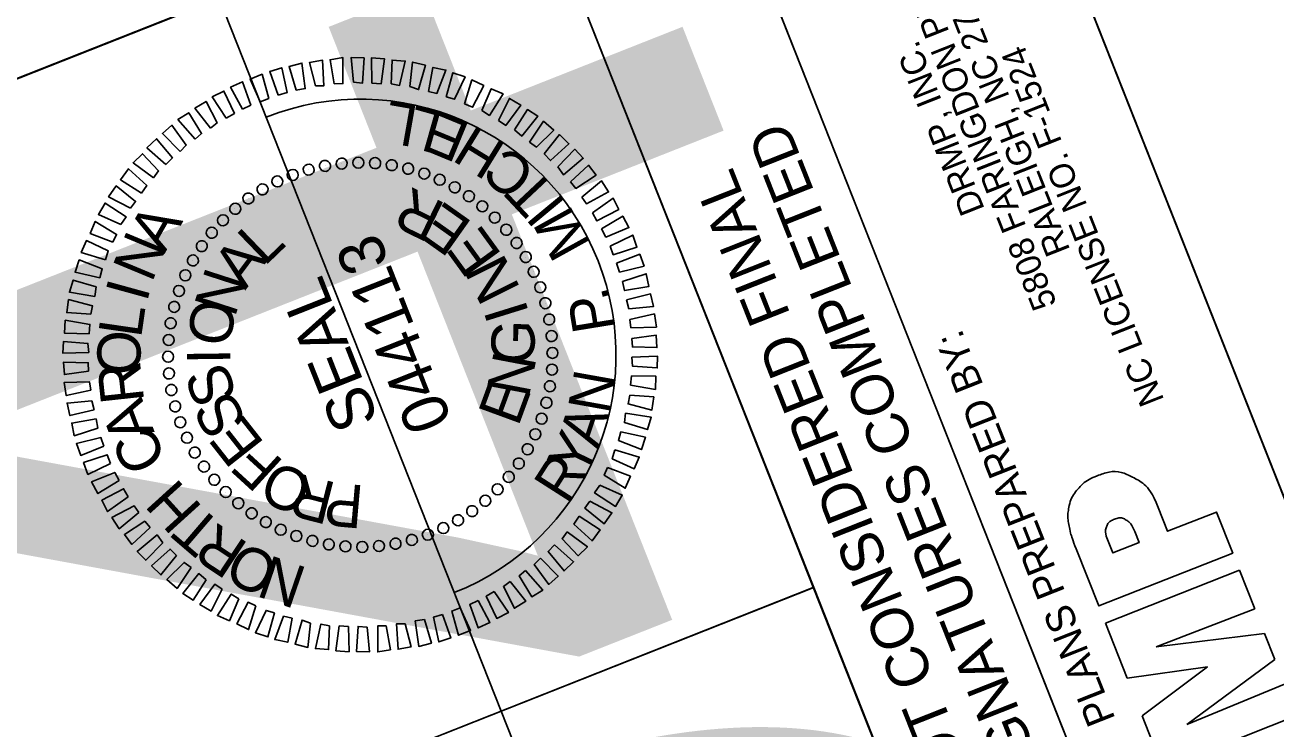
# Model space of a CAD drawing. Extents: x 1250793 to 1252430, y 745882 to 747850.
# Drawn here: x 1250893.3 to 1251056.5, y 747383.5 to 747475.4 of the extents above; entities that cross this region are included whole.
import ezdxf

# ---------------------------------------------------------------- set-up
doc = ezdxf.new("R2010")
doc.units = 0
for name, color, linetype in [('Pattern 1', 7, 'Continuous'), ('Pattern 2', 7, 'Continuous'), ('Scratch_Level_0', 7, 'Continuous'), ('Scratch_Level_1', 7, 'Continuous'), ('Sheet Plan CELL', 7, 'Continuous'), ('Sheet Plan Layout CELL', 7, 'Continuous'), ('Sheet Professional Seal CELL', 7, 'Continuous'), ('Sheet Sticker Exception Certification CELL', 7, 'Continuous')]:
    doc.layers.add(name, color=color, linetype=linetype)

msp = doc.modelspace()

# ---------------------------------------------------------------- linework, layer by layer
at = {"layer": 'Pattern 1'}
for p, q in [((1251034.26, 747397.37), (1251051.74, 747404.28)), ((1251051.74, 747404.28), (1251053.73, 747399.24)), ((1251053.73, 747399.24), (1251040.88, 747394.26)), ((1251037.1, 747390.19), (1251034.26, 747397.37)), ((1251040.88, 747394.26), (1251055.01, 747396)), ((1251055.01, 747396), (1251056.35, 747392.61)), ((1251047.56, 747391.66), (1251037.1, 747390.19)), ((1251039.05, 747385.27), (1251047.56, 747391.66)), ((1251056.35, 747392.61), (1251044.88, 747384.14)), ((1251044.88, 747384.14), (1251057.63, 747389.39)), ((1251041.77, 747378.39), (1251039.05, 747385.27)), ((1251059.24, 747385.3), (1251041.77, 747378.39))]:
    msp.add_line(p, q, dxfattribs=at)
for points in [[(1251041.15, 747412.45), (1251042.37, 747409.35), (1251048.74, 747411.86), (1251050.86, 747406.51), (1251033.38, 747399.6), (1251030.43, 747407.05)], [(1251034.52, 747408.28), (1251035.21, 747406.52), (1251038.64, 747407.87), (1251038.07, 747409.31)]]:
    msp.add_lwpolyline(points, dxfattribs=at)
for points in [[(1251030.43, 747407.05), (1251029.97, 747408.21), (1251029.66, 747409.21), (1251029.5, 747410.03), (1251029.35, 747410.85), (1251029.32, 747411.58), (1251029.43, 747412.21), (1251029.62, 747413.24), (1251030.03, 747414.12), (1251030.65, 747414.85), (1251031.27, 747415.58), (1251032.08, 747416.15), (1251033.08, 747416.54), (1251034.75, 747417.2), (1251036.32, 747417.16), (1251037.8, 747416.4), (1251039.29, 747415.65), (1251040.4, 747414.34), (1251041.15, 747412.45)], [(1251038.07, 747409.31), (1251037.79, 747410.03), (1251037.41, 747410.54), (1251036.95, 747410.82), (1251036.49, 747411.1), (1251035.99, 747411.14), (1251035.45, 747410.92), (1251034.9, 747410.7), (1251034.54, 747410.37), (1251034.38, 747409.92), (1251034.22, 747409.46), (1251034.26, 747408.92), (1251034.52, 747408.28)]]:
    msp.add_open_spline(points, degree=3, dxfattribs=at)
at = {"layer": 'Scratch_Level_0'}
msp.add_lwpolyline([(1250981.23, 747503.62), (1251016.51, 747517.57), (1251090.07, 747331.55), (1251054.79, 747317.6)], close=True, dxfattribs=at)
msp.add_arc((1250937.02, 747432.38), 33.36, 291.5748, 111.5748, dxfattribs=at)
at = {"layer": 'Scratch_Level_1'}
msp.add_line((1250974.08, 747338.64), (1250879.11, 747578.82), dxfattribs=at)
at = {"layer": 'Sheet Plan CELL'}
msp.add_line((1250891.55, 747360.62), (1250996.12, 747401.99), dxfattribs=at)
for points in [[(1250819.83, 747439.83), (1251371.41, 746044.88), (1252347.85, 746430.97), (1251796.28, 747825.9)], [(1252347.85, 746430.97), (1251371.44, 746044.87), (1250893.39, 747253.76), (1251032.94, 747308.96), (1250959.39, 747494.98), (1251796.28, 747825.9)], [(1250891.55, 747360.62), (1250854.77, 747453.6), (1250959.39, 747494.98), (1250996.18, 747401.99)], [(1250928.33, 747267.58), (1250891.55, 747360.62), (1250996.18, 747401.99), (1251032.94, 747308.96)]]:
    msp.add_lwpolyline(points, close=True, dxfattribs=at)
at = {"layer": 'Sheet Plan Layout CELL'}
for points in [[(1251371.44, 746044.87), (1252347.85, 746430.97), (1251796.29, 747825.89), (1251016.52, 747517.56), (1251104.49, 747295.07), (1250907.82, 747217.3)], [(1251104.49, 747295.07), (1251016.51, 747517.58), (1250819.83, 747439.84), (1250907.82, 747217.3)]]:
    msp.add_lwpolyline(points, close=True, dxfattribs=at)
at = {"layer": 'Sheet Professional Seal CELL'}
for p, q in [((1250930.31, 747456.56), (1250930.31, 747456.56)), ((1250932.43, 747457.02), (1250932.43, 747457.02)), ((1250934.55, 747457.38), (1250934.55, 747457.38)), ((1250936.76, 747457.5), (1250936.76, 747457.5)), ((1250938.95, 747457.4), (1250938.95, 747457.4)), ((1250941.13, 747457.18), (1250941.13, 747457.18)), ((1250943.27, 747456.68), (1250943.27, 747456.68)), ((1250926.18, 747455.03), (1250926.18, 747455.03)), ((1250928.2, 747455.89), (1250928.2, 747455.89)), ((1250945.39, 747456.07), (1250945.39, 747456.07)), ((1250947.38, 747455.25), (1250947.38, 747455.25)), ((1250924.29, 747453.96), (1250924.29, 747453.96)), ((1250949.39, 747454.26), (1250949.39, 747454.26)), ((1250922.39, 747452.78), (1250922.39, 747452.78)), ((1250951.19, 747453.09), (1250951.19, 747453.09)), ((1250952.96, 747451.75), (1250952.96, 747451.75)), ((1250919.09, 747449.97), (1250919.09, 747449.97)), ((1250920.66, 747451.45), (1250920.66, 747451.45)), ((1250954.61, 747450.31), (1250954.61, 747450.31)), ((1250917.65, 747448.33), (1250917.65, 747448.33)), ((1250956.09, 747448.74), (1250956.09, 747448.74)), ((1250957.42, 747447.01), (1250957.42, 747447.01)), ((1250916.3, 747446.56), (1250916.3, 747446.56)), ((1250958.6, 747445.11), (1250958.6, 747445.11)), ((1250915.13, 747444.75), (1250915.13, 747444.75)), ((1250914.15, 747442.75), (1250914.15, 747442.75)), ((1250959.67, 747443.22), (1250959.67, 747443.22)), ((1250913.33, 747440.76), (1250913.33, 747440.76)), ((1250960.52, 747441.19), (1250960.52, 747441.19)), ((1250912.71, 747438.63), (1250912.71, 747438.63)), ((1250961.19, 747439.09), (1250961.19, 747439.09)), ((1250961.66, 747436.96), (1250961.66, 747436.96)), ((1250912.21, 747436.5), (1250912.21, 747436.5)), ((1250912, 747434.32), (1250912, 747434.32)), ((1250962.01, 747434.84), (1250962.01, 747434.84)), ((1250911.9, 747432.13), (1250911.9, 747432.13)), ((1250937.02, 747432.38), (1250937.02, 747432.38)), ((1250962.13, 747432.63), (1250962.13, 747432.63)), ((1250962.03, 747430.44), (1250962.03, 747430.44)), ((1250912.02, 747429.92), (1250912.02, 747429.92)), ((1250912.37, 747427.8), (1250912.37, 747427.8)), ((1250961.82, 747428.26), (1250961.82, 747428.26)), ((1250912.84, 747425.67), (1250912.84, 747425.67)), ((1250961.32, 747426.13), (1250961.32, 747426.13)), ((1250960.7, 747424.01), (1250960.7, 747424.01)), ((1250913.51, 747423.57), (1250913.51, 747423.57)), ((1250914.36, 747421.54), (1250914.36, 747421.54)), ((1250959.88, 747422.01), (1250959.88, 747422.01)), ((1250915.43, 747419.65), (1250915.43, 747419.65)), ((1250958.9, 747420.01), (1250958.9, 747420.01)), ((1250916.61, 747417.75), (1250916.61, 747417.75)), ((1250957.73, 747418.2), (1250957.73, 747418.2)), ((1250917.94, 747416.02), (1250917.94, 747416.02)), ((1250956.39, 747416.44), (1250956.39, 747416.44)), ((1250919.42, 747414.46), (1250919.42, 747414.46)), ((1250954.94, 747414.79), (1250954.94, 747414.79)), ((1250921.07, 747413.01), (1250921.07, 747413.01)), ((1250953.37, 747413.31), (1250953.37, 747413.31)), ((1250922.84, 747411.67), (1250922.84, 747411.67)), ((1250949.74, 747410.8), (1250949.74, 747410.8)), ((1250951.64, 747411.98), (1250951.64, 747411.98)), ((1250924.64, 747410.5), (1250924.64, 747410.5)), ((1250926.65, 747409.52), (1250926.65, 747409.52)), ((1250947.85, 747409.73), (1250947.85, 747409.73)), ((1250928.64, 747408.69), (1250928.64, 747408.69)), ((1250930.76, 747408.08), (1250930.76, 747408.08)), ((1250932.9, 747407.58), (1250932.9, 747407.58)), ((1250941.6, 747407.74), (1250941.6, 747407.74)), ((1250943.73, 747408.2), (1250943.73, 747408.2)), ((1250945.83, 747408.87), (1250945.83, 747408.87)), ((1250935.08, 747407.37), (1250935.08, 747407.37)), ((1250937.27, 747407.26), (1250937.27, 747407.26)), ((1250939.48, 747407.39), (1250939.48, 747407.39))]:
    msp.add_line(p, q, dxfattribs=at)
for points in [[(1250933.62, 747467.76), (1250933.08, 747470.88), (1250934.75, 747471.16), (1250934.74, 747467.77)], [(1250936.13, 747467.95), (1250935.82, 747471.16), (1250937.5, 747471.12), (1250937.3, 747467.82)], [(1250938.54, 747467.82), (1250938.47, 747471.13), (1250940.19, 747471), (1250939.75, 747467.76)], [(1250926.3, 747466.27), (1250925.2, 747469.33), (1250926.77, 747469.84), (1250927.46, 747466.61)], [(1250928.63, 747466.92), (1250927.73, 747470), (1250929.39, 747470.44), (1250929.84, 747467.13)], [(1250931.15, 747467.48), (1250930.38, 747470.51), (1250932.09, 747470.81), (1250932.27, 747467.5)], [(1250941.05, 747467.74), (1250941.16, 747470.85), (1250942.88, 747470.72), (1250942.15, 747467.53)], [(1250943.49, 747467.41), (1250943.85, 747470.57), (1250945.52, 747470.16), (1250944.62, 747467)], [(1250945.9, 747466.76), (1250946.49, 747469.89), (1250948.18, 747469.54), (1250947.02, 747466.5)], [(1250921.65, 747464.43), (1250920.09, 747467.3), (1250921.63, 747468.02), (1250922.73, 747464.96)], [(1250923.96, 747465.39), (1250922.63, 747468.36), (1250924.21, 747468.99), (1250925.08, 747465.83)], [(1250948.22, 747466.06), (1250949.07, 747469.19), (1250950.69, 747468.65), (1250949.31, 747465.74)], [(1250950.63, 747465.13), (1250951.59, 747468.26), (1250953.12, 747467.52), (1250951.66, 747464.68)], [(1250919.53, 747463.27), (1250917.69, 747466.03), (1250919.21, 747466.8), (1250920.58, 747463.89)], [(1250952.86, 747464.24), (1250954.1, 747467.09), (1250955.65, 747466.42), (1250953.86, 747463.61)], [(1250917.47, 747461.97), (1250915.43, 747464.55), (1250916.9, 747465.45), (1250918.33, 747462.63)], [(1250955.04, 747462.95), (1250956.48, 747465.83), (1250957.95, 747464.96), (1250955.99, 747462.31)], [(1250915.46, 747460.52), (1250913.21, 747463.08), (1250914.63, 747463.96), (1250916.3, 747461.24)], [(1250957.13, 747461.73), (1250958.82, 747464.39), (1250960.18, 747463.53), (1250958.09, 747460.93)], [(1250913.52, 747458.9), (1250911.19, 747461.26), (1250912.43, 747462.34), (1250914.31, 747459.75)], [(1250959.1, 747460.15), (1250960.93, 747462.86), (1250962.25, 747461.71), (1250960.01, 747459.49)], [(1250911.66, 747457.2), (1250909.18, 747459.39), (1250910.43, 747460.58), (1250912.5, 747458.07)], [(1250961.01, 747458.59), (1250963.02, 747461.11), (1250964.25, 747459.92), (1250961.83, 747457.73)], [(1250910.03, 747455.48), (1250907.37, 747457.44), (1250908.58, 747458.61), (1250910.69, 747456.38)], [(1250962.79, 747456.93), (1250965.01, 747459.21), (1250966.12, 747458.03), (1250963.53, 747455.88)], [(1250908.46, 747453.46), (1250905.72, 747455.22), (1250906.77, 747456.66), (1250909.14, 747454.48)], [(1250964.44, 747454.95), (1250966.81, 747457.12), (1250967.79, 747455.84), (1250965.15, 747454.1)], [(1250965.93, 747452.95), (1250968.47, 747455.09), (1250969.42, 747453.64), (1250966.54, 747452.07)], [(1250907.04, 747451.5), (1250904.18, 747453), (1250905.18, 747454.42), (1250907.7, 747452.4)], [(1250905.77, 747449.38), (1250902.84, 747450.7), (1250903.71, 747452.17), (1250906.45, 747450.4)], [(1250967.32, 747450.92), (1250970, 747452.84), (1250970.75, 747451.36), (1250967.9, 747449.86)], [(1250968.48, 747448.8), (1250971.26, 747450.49), (1250972.07, 747448.98), (1250969.06, 747447.74)], [(1250904.74, 747447.09), (1250901.77, 747448.23), (1250902.44, 747449.79), (1250905.21, 747448.09)], [(1250903.78, 747444.78), (1250900.61, 747445.73), (1250901.28, 747447.29), (1250904.13, 747445.94)], [(1250969.63, 747446.57), (1250972.56, 747448), (1250973.12, 747446.44), (1250970.03, 747445.43)], [(1250970.47, 747444.32), (1250973.49, 747445.51), (1250974.05, 747443.96), (1250970.86, 747443.18)], [(1250903.04, 747442.44), (1250899.8, 747443.15), (1250900.34, 747444.76), (1250903.34, 747443.58)], [(1250902.39, 747439.98), (1250899.05, 747440.54), (1250899.55, 747442.14), (1250902.55, 747441.23)], [(1250971.25, 747441.94), (1250974.34, 747442.95), (1250974.67, 747441.3), (1250971.5, 747440.75)], [(1250971.76, 747439.56), (1250974.9, 747440.32), (1250975.28, 747438.69), (1250972.06, 747438.39)], [(1250901.86, 747437.67), (1250898.71, 747437.88), (1250898.95, 747439.59), (1250902.06, 747438.78)], [(1250901.63, 747435.11), (1250898.43, 747435.19), (1250898.51, 747436.89), (1250901.74, 747436.34)], [(1250972.19, 747436.99), (1250975.39, 747437.72), (1250975.65, 747435.99), (1250972.34, 747435.92)], [(1250901.58, 747432.67), (1250898.22, 747432.58), (1250898.27, 747434.1), (1250901.48, 747433.87)], [(1250972.46, 747434.52), (1250975.62, 747434.96), (1250975.73, 747433.33), (1250972.52, 747433.41)], [(1250972.45, 747432.09), (1250975.81, 747432.18), (1250975.76, 747430.66), (1250972.55, 747430.89)], [(1250901.57, 747430.25), (1250898.41, 747429.8), (1250898.3, 747431.43), (1250901.51, 747431.35)], [(1250901.84, 747427.78), (1250898.64, 747427.05), (1250898.39, 747428.77), (1250901.69, 747428.84)], [(1250972.4, 747429.65), (1250975.6, 747429.57), (1250975.52, 747427.87), (1250972.29, 747428.43)], [(1250972.17, 747427.09), (1250975.32, 747426.88), (1250975.08, 747425.17), (1250971.97, 747425.98)], [(1250902.27, 747425.2), (1250899.13, 747424.44), (1250898.76, 747426.07), (1250901.97, 747426.37)], [(1250902.78, 747422.82), (1250899.69, 747421.81), (1250899.36, 747423.46), (1250902.53, 747424.01)], [(1250971.64, 747424.78), (1250974.98, 747424.22), (1250974.48, 747422.62), (1250971.48, 747423.54)], [(1250971, 747422.32), (1250974.23, 747421.61), (1250973.69, 747420), (1250970.69, 747421.18)], [(1250903.56, 747420.44), (1250900.54, 747419.25), (1250899.98, 747420.8), (1250903.17, 747421.58)], [(1250904.4, 747418.19), (1250901.47, 747416.77), (1250900.91, 747418.32), (1250904, 747419.33)], [(1250970.25, 747419.98), (1250973.42, 747419.03), (1250972.75, 747417.48), (1250969.9, 747418.82)], [(1250969.29, 747417.67), (1250972.26, 747416.53), (1250971.59, 747414.97), (1250968.82, 747416.68)], [(1250905.55, 747415.96), (1250902.78, 747414.27), (1250901.96, 747415.78), (1250904.97, 747417.02)], [(1250906.71, 747413.84), (1250904.03, 747411.92), (1250903.28, 747413.4), (1250906.13, 747414.9)], [(1250968.26, 747415.38), (1250971.19, 747414.07), (1250970.33, 747412.59), (1250967.58, 747414.36)], [(1250908.1, 747411.81), (1250905.56, 747409.67), (1250904.61, 747411.13), (1250907.49, 747412.69)], [(1250966.99, 747413.27), (1250969.85, 747411.76), (1250968.85, 747410.34), (1250966.33, 747412.36)], [(1250965.57, 747411.3), (1250968.31, 747409.54), (1250967.26, 747408.1), (1250964.89, 747410.28)], [(1250909.59, 747409.82), (1250907.22, 747407.64), (1250906.24, 747408.92), (1250908.88, 747410.66)], [(1250964, 747409.28), (1250966.66, 747407.32), (1250965.45, 747406.15), (1250963.34, 747408.38)], [(1250911.24, 747407.83), (1250909.02, 747405.56), (1250907.91, 747406.73), (1250910.5, 747408.88)], [(1250962.37, 747407.56), (1250964.85, 747405.37), (1250963.6, 747404.18), (1250961.53, 747406.69)], [(1250913.02, 747406.17), (1250911.01, 747403.65), (1250909.79, 747404.84), (1250912.2, 747407.03)], [(1250960.51, 747405.86), (1250962.84, 747403.5), (1250961.6, 747402.42), (1250959.72, 747405.01)], [(1250914.93, 747404.61), (1250913.1, 747401.9), (1250911.78, 747403.05), (1250914.02, 747405.28)], [(1250958.57, 747404.24), (1250960.82, 747401.68), (1250959.4, 747400.8), (1250957.73, 747403.53)], [(1250916.9, 747403.03), (1250915.21, 747400.37), (1250913.85, 747401.23), (1250915.94, 747403.83)], [(1250956.56, 747402.8), (1250958.61, 747400.22), (1250957.13, 747399.31), (1250955.7, 747402.13)], [(1250918.99, 747401.81), (1250917.55, 747398.93), (1250916.08, 747399.8), (1250918.04, 747402.46)], [(1250921.17, 747400.52), (1250919.93, 747397.67), (1250918.38, 747398.34), (1250920.17, 747401.15)], [(1250954.5, 747401.5), (1250956.34, 747398.73), (1250954.82, 747397.97), (1250953.45, 747400.87)], [(1250923.4, 747399.63), (1250922.44, 747396.51), (1250920.91, 747397.25), (1250922.37, 747400.08)], [(1250950.07, 747399.37), (1250951.4, 747396.4), (1250949.82, 747395.78), (1250948.95, 747398.93)], [(1250952.38, 747400.33), (1250953.94, 747397.46), (1250952.4, 747396.74), (1250951.3, 747399.8)], [(1250925.81, 747398.7), (1250924.96, 747395.57), (1250923.34, 747396.11), (1250924.72, 747399.02)], [(1250928.13, 747398.01), (1250927.54, 747394.87), (1250925.85, 747395.22), (1250927.01, 747398.26)], [(1250930.54, 747397.35), (1250930.18, 747394.19), (1250928.51, 747394.61), (1250929.41, 747397.76)], [(1250945.4, 747397.85), (1250946.3, 747394.76), (1250944.65, 747394.32), (1250944.19, 747397.64)], [(1250947.73, 747398.5), (1250948.83, 747395.44), (1250947.26, 747394.92), (1250946.57, 747398.15)], [(1250932.98, 747397.02), (1250932.87, 747393.91), (1250931.15, 747394.04), (1250931.88, 747397.23)], [(1250935.49, 747396.94), (1250935.56, 747393.63), (1250933.84, 747393.76), (1250934.28, 747397)], [(1250937.91, 747396.82), (1250938.21, 747393.6), (1250936.53, 747393.64), (1250936.73, 747396.94)], [(1250940.41, 747397), (1250940.95, 747393.88), (1250939.29, 747393.6), (1250939.29, 747396.99)], [(1250942.88, 747397.28), (1250943.65, 747394.25), (1250941.94, 747393.95), (1250941.76, 747397.27)]]:
    msp.add_lwpolyline(points, close=True, dxfattribs=at)
for centre, major_axis in [((1250934.58, 747457.34), (-0.07, 0.717)), ((1250936.76, 747457.46), (-0.007, 0.72)), ((1250938.95, 747457.39), (0.056, 0.718)), ((1250928.2, 747455.86), (-0.253, 0.674)), ((1250930.28, 747456.54), (-0.193, 0.694)), ((1250932.41, 747457.03), (-0.132, 0.708)), ((1250941.12, 747457.12), (0.118, 0.71)), ((1250943.26, 747456.67), (0.179, 0.697)), ((1250945.36, 747456.03), (0.239, 0.679)), ((1250924.26, 747453.97), (-0.366, 0.62)), ((1250926.19, 747455), (-0.311, 0.649)), ((1250947.39, 747455.22), (0.298, 0.656)), ((1250949.34, 747454.23), (0.354, 0.627)), ((1250922.42, 747452.78), (-0.419, 0.586)), ((1250951.19, 747453.07), (0.407, 0.594)), ((1250920.7, 747451.43), (-0.468, 0.547)), ((1250952.94, 747451.75), (0.457, 0.556)), ((1250919.1, 747449.94), (-0.514, 0.504)), ((1250954.57, 747450.29), (0.504, 0.514)), ((1250917.64, 747448.31), (-0.556, 0.457)), ((1250956.06, 747448.69), (0.547, 0.468)), ((1250916.33, 747446.56), (-0.594, 0.407)), ((1250957.41, 747446.97), (0.586, 0.419)), ((1250915.17, 747444.7), (-0.627, 0.354)), ((1250958.61, 747445.14), (0.62, 0.366)), ((1250914.18, 747442.75), (-0.656, 0.298)), ((1250959.64, 747443.21), (0.649, 0.311)), ((1250960.5, 747441.19), (0.674, 0.253)), ((1250913.36, 747440.72), (-0.679, 0.239)), ((1250912.73, 747438.63), (-0.697, 0.179)), ((1250961.17, 747439.11), (0.694, 0.193)), ((1250912.27, 747436.49), (-0.71, 0.118)), ((1250961.67, 747436.98), (0.708, 0.132)), ((1250961.98, 747434.82), (0.717, 0.07)), ((1250912.01, 747434.32), (-0.718, 0.056)), ((1250911.94, 747432.13), (-0.72, -0.007)), ((1250962.09, 747432.63), (0.72, 0.007)), ((1250912.05, 747429.94), (-0.717, -0.07)), ((1250962.02, 747430.45), (0.718, -0.056)), ((1250961.76, 747428.27), (0.71, -0.118)), ((1250912.36, 747427.78), (-0.708, -0.132)), ((1250912.86, 747425.65), (-0.694, -0.193)), ((1250961.3, 747426.13), (0.697, -0.179)), ((1250913.53, 747423.57), (-0.674, -0.253)), ((1250960.67, 747424.04), (0.679, -0.239)), ((1250914.39, 747421.55), (-0.649, -0.311)), ((1250959.85, 747422.01), (0.656, -0.298)), ((1250958.86, 747420.06), (0.627, -0.354)), ((1250915.42, 747419.62), (-0.62, -0.366)), ((1250957.7, 747418.2), (0.594, -0.407)), ((1250916.62, 747417.79), (-0.586, -0.419)), ((1250956.39, 747416.45), (0.556, -0.457)), ((1250917.97, 747416.07), (-0.547, -0.468)), ((1250954.93, 747414.83), (0.514, -0.504)), ((1250919.46, 747414.47), (-0.504, -0.514)), ((1250953.33, 747413.33), (0.468, -0.547)), ((1250921.09, 747413.01), (-0.457, -0.556)), ((1250922.84, 747411.69), (-0.407, -0.594)), ((1250951.61, 747411.98), (0.419, -0.586)), ((1250924.69, 747410.54), (-0.354, -0.627)), ((1250949.77, 747410.79), (0.366, -0.62)), ((1250926.64, 747409.55), (-0.298, -0.656)), ((1250928.67, 747408.73), (-0.239, -0.679)), ((1250945.83, 747408.9), (0.253, -0.674)), ((1250947.84, 747409.76), (0.311, -0.649)), ((1250930.77, 747408.09), (-0.179, -0.697)), ((1250932.91, 747407.64), (-0.118, -0.71)), ((1250935.08, 747407.38), (-0.056, -0.718)), ((1250937.27, 747407.3), (0.007, -0.72)), ((1250939.45, 747407.42), (0.07, -0.717)), ((1250941.62, 747407.73), (0.132, -0.708)), ((1250943.75, 747408.22), (0.193, -0.694))]:
    msp.add_ellipse(centre, major_axis=major_axis, ratio=0.999708, dxfattribs=at)
at = {"layer": 'Sheet Sticker Exception Certification CELL'}
for p, q in [((1250981.23, 747503.62), (1251054.79, 747317.6)), ((1250981.23, 747503.62), (1251054.79, 747317.6)), ((1251032.94, 747308.96), (1250959.38, 747494.98)), ((1251032.94, 747308.96), (1250959.38, 747494.98))]:
    msp.add_line(p, q, dxfattribs=at)

# ---------------------------------------------------------------- texts
at = {"layer": 'Pattern 2'}
for s, height, p in [('NC LICENSE NO. F-1524    (919) 872-5115', 3.25, (1251041.95, 747426.47)), ('5808 FARINGDON PLACE', 3.25, (1251027.95, 747439.01)), ('RALEIGH, NC 27609', 3.25, (1251029.69, 747446.05)), ('DRMP, INC.', 3.25, (1251018.53, 747451.38)), ('PLANS PREPARED BY:', 3.75, (1251035.59, 747384.85))]:
    msp.add_text(s, height=height, rotation=111.5748, dxfattribs=at).set_placement(p)
at = {"layer": 'Sheet Plan Layout CELL'}
msp.add_text('04', height=131.25, rotation=111.5743, dxfattribs=at).set_placement((1251042.72, 747314.2))
at = {"layer": 'Sheet Professional Seal CELL'}
for s, height, rotation, p in [('L', 5.5, 169.9942, (1250944.8, 747464.89)), ('L', 5.5, 164.184, (1250948.05, 747463.93)), ('E', 5.5, 157.601, (1250951.59, 747462.46)), ('H', 5.5, 148.3562, (1250956.24, 747459.73)), ('C', 5.5, 139.4835, (1250960.22, 747456.43)), ('T', 5.5, 133.1867, (1250962.72, 747453.74)), ('R', 5.64, 154.0562, (1250948.34, 747452.02)), ('I', 5.5, 129.6662, (1250963.99, 747452.13)), ('E', 5.64, 144.6989, (1250951.83, 747449.58)), ('M', 5.5, 118.9904, (1250967.18, 747446.79)), ('A', 5.64, 60.1919, (1250911.45, 747445.5)), ('N', 5.64, 67.3937, (1250909.79, 747441.67)), ('L', 5.64, 43.9756, (1250924.48, 747443.82)), ('E', 5.64, 125.9865, (1250955.59, 747445.37)), ('044113', 5.998, 111.5748, (1250949.06, 747423.69)), ('A', 5.64, 53.335, (1250921.99, 747440.74)), ('N', 5.64, 116.6312, (1250957.97, 747440.99)), ('N', 5.64, 72.0514, (1250920.62, 747437.13)), ('I', 5.64, 74.5949, (1250909.14, 747439.1)), ('SEAL', 5.998, 111.5748, (1250939.46, 747423.89)), ('.', 5.5, 105.8101, (1250969.67, 747439.53)), ('L', 5.64, 81.7957, (1250908.4, 747434.45)), ('O', 5.64, 81.4083, (1250919.99, 747433.28)), ('I', 5.64, 107.276, (1250959.06, 747437.82)), ('P', 5.5, 99.2271, (1250970.27, 747435.74)), ('O', 5.64, 88.9959, (1250908.3, 747429.68)), ('G', 5.64, 88.565, (1250959.7, 747431.03)), ('I', 5.64, 90.7644, (1250920.07, 747431.17)), ('N', 5.64, 79.2087, (1250959.01, 747426.67)), ('R', 5.64, 96.1959, (1250908.83, 747426.29)), ('S', 5.64, 109.4752, (1250921.01, 747426.91)), ('E', 5.64, 69.8517, (1250957.6, 747422.88)), ('N', 5.5, 79.8502, (1250969.5, 747424.52)), ('S', 5.64, 118.8304, (1250922.38, 747423.58)), ('A', 5.64, 110.5951, (1250910.19, 747422.31)), ('E', 5.64, 128.1858, (1250924.62, 747420.76)), ('A', 5.5, 71.6644, (1250968.05, 747419.97)), ('C', 5.64, 117.7946, (1250911.92, 747418.75)), ('Y', 5.5, 64.3373, (1250966.21, 747416.11)), ('F', 5.64, 137.5418, (1250927.19, 747418.33)), ('R', 5.5, 57.4109, (1250964.04, 747412.71)), ('O', 5.64, 156.256, (1250931.15, 747416.35)), ('H', 5.64, 132.1943, (1250916.57, 747412.42)), ('R', 5.64, 165.6144, (1250934.07, 747415.62)), ('P', 5.64, 174.9737, (1250937.63, 747415.31)), ('T', 5.64, 139.3946, (1250919.3, 747410)), ('R', 5.64, 146.5953, (1250922.6, 747407.65)), ('O', 5.64, 153.7965, (1250926.75, 747405.58)), ('N', 5.64, 160.9983, (1250930.29, 747404.51))]:
    msp.add_text(s, height=height, rotation=rotation, dxfattribs=at).set_placement(p)
at = {"layer": 'Sheet Sticker Exception Certification CELL'}
for s, p in [('UNLESS ALL SIGNATURES COMPLETED', (1251044.86, 747330.87)), ('UNLESS ALL SIGNATURES COMPLETED', (1251044.86, 747330.87)), ('DOCUMENT NOT CONSIDERED FINAL', (1251034.81, 747332.35)), ('DOCUMENT NOT CONSIDERED FINAL', (1251034.81, 747332.35))]:
    msp.add_text(s, height=5.5, rotation=111.5743, dxfattribs=at).set_placement(p)

doc.saveas('drawing.dxf')
